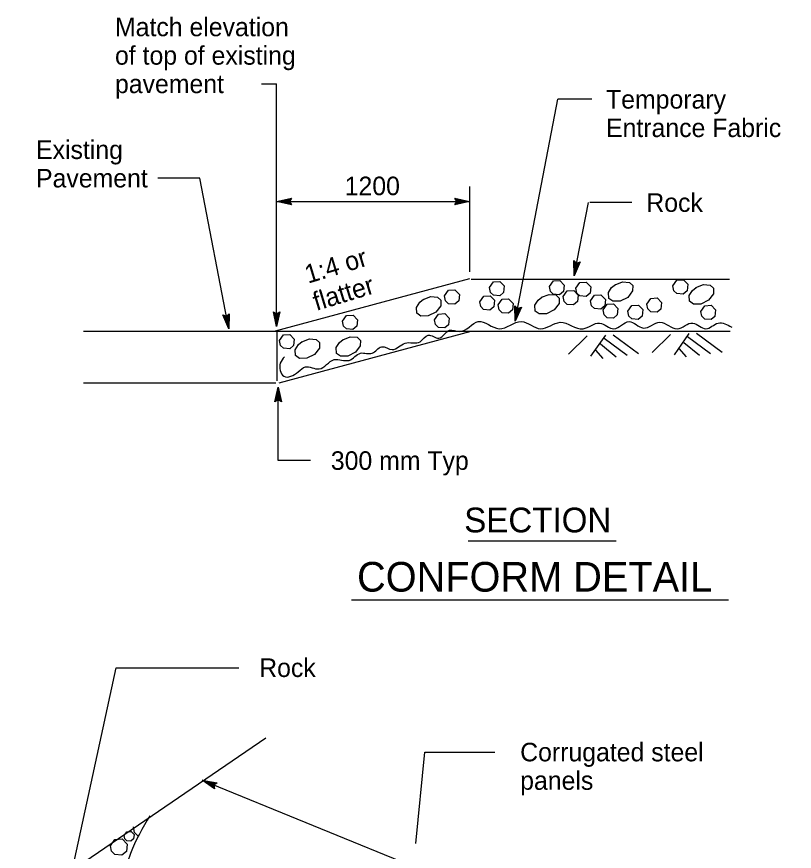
# Model space of a CAD drawing. Extents: x 6707406 to 6714471, y 1868570 to 1872341.
# Drawn here: x 6709787.7 to 6710089.4, y 1870437 to 1870760.9 of the extents above; entities that cross this region are included whole.
import ezdxf

# ---------------------------------------------------------------- set-up
doc = ezdxf.new("R2010")
doc.units = 0
for name, color, linetype in [('56 Stg 3 Anno', 7, 'Continuous'), ('57 Undefined', 7, 'Continuous'), ('59 Soundwall Ann', 7, 'Continuous'), ('60 Nongeo Data', 7, 'Continuous')]:
    doc.layers.add(name, color=color, linetype=linetype)

msp = doc.modelspace()

# ---------------------------------------------------------------- linework, layer by layer
at = {"layer": '56 Stg 3 Anno'}
for p, q in [((6709882.69, 1870734.85), (6709888.58, 1870734.85)), ((6709888.58, 1870640.62), (6709888.58, 1870734.85)), ((6709981.16, 1870642.76), (6709997.7, 1870728.84)), ((6710010.8, 1870728.84), (6709997.7, 1870728.84)), ((6709858.77, 1870698.25), (6709842.43, 1870698.25)), ((6709870.01, 1870639.76), (6709858.77, 1870698.25)), ((6709963.41, 1870695.06), (6709963.41, 1870661.92)), ((6709888.58, 1870689.24), (6709894.34, 1870690.52)), ((6709894.34, 1870690.52), (6709893.58, 1870689.24)), ((6709894.34, 1870690.52), (6709894.34, 1870690.52)), ((6709958.42, 1870689.24), (6709957.65, 1870690.53)), ((6709957.65, 1870690.53), (6709957.65, 1870690.53)), ((6709957.65, 1870690.53), (6709963.41, 1870689.24)), ((6709888.58, 1870689.24), (6709963.41, 1870689.24)), ((6709894.34, 1870687.95), (6709888.58, 1870689.24)), ((6709888.58, 1870689.24), (6709888.58, 1870689.24)), ((6709894.14, 1870688.3), (6709889.91, 1870689.24)), ((6709889.92, 1870689.24), (6709894.12, 1870690.17)), ((6709891.24, 1870689.24), (6709893.95, 1870689.84)), ((6709893.91, 1870688.64), (6709891.24, 1870689.24)), ((6709892.56, 1870689.24), (6709893.72, 1870689.49)), ((6709893.74, 1870688.97), (6709892.56, 1870689.24)), ((6709893.58, 1870689.24), (6709894.34, 1870687.95)), ((6709894.34, 1870687.95), (6709894.34, 1870687.95)), ((6709963.41, 1870689.24), (6709957.65, 1870687.96)), ((6709957.65, 1870687.96), (6709958.42, 1870689.24)), ((6709957.65, 1870687.96), (6709957.65, 1870687.96)), ((6709957.86, 1870690.19), (6709962.09, 1870689.24)), ((6709962.08, 1870689.24), (6709957.88, 1870688.31)), ((6709960.76, 1870689.24), (6709958.05, 1870688.64)), ((6709958.09, 1870689.84), (6709960.76, 1870689.24)), ((6709958.26, 1870689.51), (6709959.44, 1870689.24)), ((6709959.44, 1870689.24), (6709958.27, 1870688.99)), ((6709963.41, 1870689.24), (6709963.41, 1870689.24)), ((6710004.04, 1870660.38), (6710009.5, 1870688.77)), ((6710026.4, 1870688.77), (6710010.05, 1870688.77)), ((6710004.04, 1870660.38), (6710003.87, 1870666.28)), ((6710003.87, 1870666.28), (6710003.87, 1870666.28)), ((6710003.87, 1870666.28), (6710004.98, 1870665.28)), ((6710006.39, 1870665.79), (6710004.04, 1870660.38)), ((6710004.29, 1870661.69), (6710004.17, 1870665.99)), ((6710006.02, 1870665.65), (6710004.29, 1870661.68)), ((6710004.54, 1870662.98), (6710004.46, 1870665.76)), ((6710005.63, 1870665.5), (6710004.54, 1870662.98)), ((6710004.79, 1870664.28), (6710004.76, 1870665.47)), ((6710005.28, 1870665.39), (6710004.79, 1870664.28)), ((6710004.98, 1870665.28), (6710006.39, 1870665.79)), ((6710006.39, 1870665.79), (6710006.39, 1870665.79)), ((6710004.04, 1870660.38), (6710004.04, 1870660.38)), ((6709981.16, 1870642.76), (6709981, 1870648.65)), ((6709981, 1870648.65), (6709981, 1870648.65)), ((6709981, 1870648.65), (6709982.1, 1870647.66)), ((6709981.41, 1870644.07), (6709981.29, 1870648.37)), ((6709870.01, 1870639.76), (6709867.67, 1870645.17)), ((6709867.67, 1870645.17), (6709867.67, 1870645.17)), ((6709867.67, 1870645.17), (6709869.07, 1870644.66)), ((6709869.07, 1870644.66), (6709870.19, 1870645.66)), ((6709869.59, 1870645.1), (6709869.51, 1870642.36)), ((6709869.89, 1870645.39), (6709869.76, 1870641.06)), ((6709870.19, 1870645.66), (6709870.01, 1870639.76)), ((6709870.19, 1870645.66), (6709870.19, 1870645.66)), ((6709888.58, 1870640.62), (6709887.31, 1870646.38)), ((6709887.31, 1870646.38), (6709887.31, 1870646.38)), ((6709887.31, 1870646.38), (6709888.58, 1870645.61)), ((6709888.58, 1870641.95), (6709887.65, 1870646.15)), ((6709888.59, 1870643.27), (6709887.98, 1870645.98)), ((6709888.59, 1870644.6), (6709888.33, 1870645.76)), ((6709888.58, 1870645.61), (6709889.87, 1870646.38)), ((6709889.87, 1870646.38), (6709888.58, 1870640.62)), ((6709889.53, 1870646.17), (6709888.58, 1870641.94)), ((6709889.18, 1870645.94), (6709888.59, 1870643.27)), ((6709888.85, 1870645.78), (6709888.59, 1870644.6)), ((6709889.87, 1870646.38), (6709889.87, 1870646.38)), ((6709983.51, 1870648.17), (6709981.16, 1870642.76)), ((6709983.14, 1870648.03), (6709981.41, 1870644.06)), ((6709981.67, 1870645.36), (6709981.59, 1870648.14)), ((6709982.76, 1870647.88), (6709981.67, 1870645.36)), ((6709981.92, 1870646.66), (6709981.88, 1870647.85)), ((6709982.4, 1870647.77), (6709981.92, 1870646.66)), ((6709982.1, 1870647.66), (6709983.51, 1870648.17)), ((6709983.51, 1870648.17), (6709983.51, 1870648.17)), ((6709869.76, 1870641.07), (6709868.05, 1870645.02)), ((6709869.51, 1870642.36), (6709868.41, 1870644.91)), ((6709869.26, 1870643.67), (6709868.79, 1870644.76)), ((6709869.3, 1870644.88), (6709869.26, 1870643.67)), ((6709981.16, 1870642.76), (6709981.16, 1870642.76)), ((6709870.01, 1870639.76), (6709870.01, 1870639.76)), ((6709888.58, 1870640.62), (6709888.58, 1870640.62)), ((6709887.85, 1870611.42), (6709889.14, 1870617.18)), ((6709889.14, 1870588.65), (6709889.14, 1870617.18)), ((6709889.14, 1870617.18), (6709889.14, 1870617.18)), ((6709889.14, 1870617.18), (6709890.42, 1870611.42)), ((6709888.2, 1870611.63), (6709889.14, 1870615.86)), ((6709888.54, 1870611.86), (6709889.14, 1870614.53)), ((6709888.87, 1870612.03), (6709889.14, 1870613.21)), ((6709889.14, 1870615.85), (6709890.07, 1870611.65)), ((6709889.14, 1870614.53), (6709889.74, 1870611.82)), ((6709889.14, 1870613.21), (6709889.39, 1870612.05)), ((6709889.14, 1870612.19), (6709887.85, 1870611.42)), ((6709887.85, 1870611.42), (6709887.85, 1870611.42)), ((6709890.42, 1870611.42), (6709889.14, 1870612.19)), ((6709890.42, 1870611.42), (6709890.42, 1870611.42)), ((6709901.67, 1870588.65), (6709889.14, 1870588.65)), ((6709803.25, 1870401.82), (6709826.34, 1870508.28)), ((6709826.34, 1870508.28), (6709873.95, 1870508.28)), ((6709942.55, 1870440.07), (6709946.04, 1870475.53)), ((6709946.04, 1870475.53), (6709973.16, 1870475.53)), ((6709859.63, 1870464.61), (6710181.3, 1870333.54)), ((6709864.48, 1870461.25), (6709859.63, 1870464.61)), ((6709859.63, 1870464.61), (6709859.63, 1870464.61)), ((6709859.63, 1870464.61), (6709865.45, 1870463.62)), ((6709864.42, 1870461.64), (6709860.86, 1870464.11)), ((6709860.87, 1870464.11), (6709865.11, 1870463.39)), ((6709864.34, 1870462.05), (6709862.09, 1870463.61)), ((6709862.09, 1870463.61), (6709864.83, 1870463.14)), ((6709864.31, 1870462.42), (6709863.32, 1870463.11)), ((6709863.32, 1870463.11), (6709864.49, 1870462.91)), ((6709865.45, 1870463.62), (6709864.26, 1870462.73)), ((6709864.26, 1870462.73), (6709864.48, 1870461.25)), ((6709864.48, 1870461.25), (6709864.48, 1870461.25)), ((6709865.45, 1870463.62), (6709865.45, 1870463.62))]:
    msp.add_line(p, q, dxfattribs=at)
at = {"layer": '57 Undefined'}
for p, q in [((6709962.83, 1870557.57), (6710020.27, 1870557.57)), ((6709917.65, 1870534.57), (6710063.89, 1870534.57))]:
    msp.add_line(p, q, dxfattribs=at)
at = {"layer": '59 Soundwall Ann'}
for p, q in [((6710009.02, 1870637.04), (6710001.85, 1870629.93)), ((6710016.17, 1870637.38), (6710010.38, 1870629.14)), ((6710015.62, 1870636.16), (6710024.52, 1870629.61)), ((6710019.07, 1870637.51), (6710029.02, 1870630.18)), ((6710041.37, 1870637.64), (6710034.2, 1870630.53)), ((6710048.52, 1870637.98), (6710042.74, 1870629.74)), ((6710047.97, 1870636.76), (6710056.87, 1870630.21)), ((6710051.42, 1870638.11), (6710061.38, 1870630.78)), ((6710014.18, 1870633.9), (6710020.29, 1870628.92)), ((6710046.53, 1870634.5), (6710052.64, 1870629.52)), ((6710012.24, 1870631.52), (6710015.15, 1870628.32)), ((6710044.59, 1870632.11), (6710047.5, 1870628.92))]:
    msp.add_line(p, q, dxfattribs=at)
at = {"layer": '60 Nongeo Data'}
for p, q in [((6709888.11, 1870638.95), (6709963.56, 1870659.27)), ((6709964.03, 1870658.99), (6710064.27, 1870658.99)), ((6709813.68, 1870638.93), (6709888.86, 1870638.93)), ((6709888.67, 1870638.97), (6709888.67, 1870619.57)), ((6709888.86, 1870638.93), (6709964.59, 1870638.93)), ((6709889.53, 1870618.87), (6709964.03, 1870638.93)), ((6709964.03, 1870638.93), (6710064.55, 1870638.93)), ((6709813.68, 1870618.87), (6709888.3, 1870618.87)), ((6709495.94, 1870216.26), (6709884.38, 1870481.01))]:
    msp.add_line(p, q, dxfattribs=at)
for points in [[(6709971.13, 1870655.85), (6709972.68, 1870658.05), (6709975.15, 1870658.19), (6709976.87, 1870656.41), (6709976.62, 1870653.91), (6709975.1, 1870652.64), (6709972.65, 1870652.82), (6709971.5, 1870653.93), (6709971.13, 1870655.85)], [(6709994.38, 1870656.22), (6709995.93, 1870658.43), (6709998.41, 1870658.57), (6710000.13, 1870656.78), (6709999.88, 1870654.28), (6709998.35, 1870653.01), (6709995.91, 1870653.19), (6709994.76, 1870654.3), (6709994.39, 1870656.22)], [(6710019.9, 1870656.91), (6710022.8, 1870658.05), (6710025.46, 1870657.82), (6710026.73, 1870656.62), (6710026.69, 1870654.46), (6710024.77, 1870652), (6710021.8, 1870650.52), (6710019, 1870650.47), (6710017.42, 1870651.59), (6710017.27, 1870653.82), (6710018.55, 1870655.81), (6710020.02, 1870656.98)], [(6710042.34, 1870656.49), (6710043.89, 1870658.7), (6710046.36, 1870658.84), (6710048.08, 1870657.06), (6710047.84, 1870654.55), (6710046.31, 1870653.28), (6710043.86, 1870653.46), (6710042.71, 1870654.58), (6710042.34, 1870656.49)], [(6709953.71, 1870652.52), (6709955.26, 1870654.73), (6709957.74, 1870654.87), (6709959.46, 1870653.09), (6709959.21, 1870650.59), (6709957.68, 1870649.31), (6709955.23, 1870649.49), (6709954.08, 1870650.61), (6709953.71, 1870652.52)], [(6710004.68, 1870655.56), (6710006.23, 1870657.76), (6710008.71, 1870657.9), (6710010.43, 1870656.12), (6710010.18, 1870653.62), (6710008.65, 1870652.35), (6710006.21, 1870652.52), (6710005.06, 1870653.64), (6710004.68, 1870655.55)], [(6710051.24, 1870655.8), (6710054.14, 1870656.95), (6710056.8, 1870656.72), (6710058.07, 1870655.51), (6710058.03, 1870653.35), (6710056.11, 1870650.9), (6710053.14, 1870649.41), (6710050.34, 1870649.36), (6710048.76, 1870650.48), (6710048.62, 1870652.71), (6710049.89, 1870654.7), (6710051.36, 1870655.87)], [(6709945.44, 1870651.18), (6709948.34, 1870652.33), (6709951, 1870652.09), (6709952.27, 1870650.89), (6709952.23, 1870648.73), (6709950.3, 1870646.27), (6709947.33, 1870644.79), (6709944.54, 1870644.74), (6709942.96, 1870645.86), (6709942.81, 1870648.09), (6709944.09, 1870650.08), (6709945.55, 1870651.25)], [(6709967.35, 1870650.29), (6709968.9, 1870652.5), (6709971.38, 1870652.64), (6709973.1, 1870650.86), (6709972.85, 1870648.36), (6709971.32, 1870647.08), (6709968.88, 1870647.26), (6709967.73, 1870648.38), (6709967.36, 1870650.29)], [(6709991.38, 1870652.01), (6709994.28, 1870653.16), (6709996.94, 1870652.93), (6709998.21, 1870651.73), (6709998.17, 1870649.57), (6709996.25, 1870647.11), (6709993.28, 1870645.62), (6709990.48, 1870645.58), (6709988.9, 1870646.69), (6709988.76, 1870648.92), (6709990.03, 1870650.92), (6709991.5, 1870652.09)], [(6709999.79, 1870652.29), (6710001.34, 1870654.5), (6710003.82, 1870654.64), (6710005.54, 1870652.86), (6710005.29, 1870650.36), (6710003.76, 1870649.08), (6710001.32, 1870649.26), (6710000.17, 1870650.38), (6709999.79, 1870652.29)], [(6710010.39, 1870650.66), (6710011.94, 1870652.87), (6710014.41, 1870653.01), (6710016.13, 1870651.22), (6710015.88, 1870648.72), (6710014.35, 1870647.45), (6710011.91, 1870647.63), (6710010.76, 1870648.75), (6710010.39, 1870650.66)], [(6710032.17, 1870649.41), (6710033.73, 1870651.61), (6710036.2, 1870651.75), (6710037.92, 1870649.97), (6710037.67, 1870647.47), (6710036.14, 1870646.2), (6710033.7, 1870646.37), (6710032.55, 1870647.49), (6710032.18, 1870649.4)], [(6709974.57, 1870649.07), (6709976.12, 1870651.28), (6709978.59, 1870651.42), (6709980.31, 1870649.64), (6709980.06, 1870647.13), (6709978.54, 1870645.86), (6709976.09, 1870646.04), (6709974.94, 1870647.16), (6709974.57, 1870649.07)], [(6710015.24, 1870647.1), (6710016.79, 1870649.31), (6710019.27, 1870649.45), (6710020.98, 1870647.66), (6710020.74, 1870645.16), (6710019.21, 1870643.89), (6710016.76, 1870644.07), (6710015.61, 1870645.18), (6710015.24, 1870647.1)], [(6710024.88, 1870646.67), (6710026.43, 1870648.87), (6710028.9, 1870649.02), (6710030.62, 1870647.23), (6710030.37, 1870644.73), (6710028.85, 1870643.46), (6710026.4, 1870643.64), (6710025.25, 1870644.75), (6710024.88, 1870646.67)], [(6710053.12, 1870646.55), (6710054.67, 1870648.75), (6710057.14, 1870648.9), (6710058.86, 1870647.11), (6710058.62, 1870644.61), (6710057.09, 1870643.34), (6710054.64, 1870643.52), (6710053.49, 1870644.63), (6710053.12, 1870646.55)], [(6709914.17, 1870642.77), (6709915.72, 1870644.98), (6709918.2, 1870645.12), (6709919.92, 1870643.33), (6709919.67, 1870640.83), (6709918.14, 1870639.56), (6709915.69, 1870639.74), (6709914.55, 1870640.85), (6709914.17, 1870642.77)], [(6709949.81, 1870643.33), (6709951.36, 1870645.53), (6709953.84, 1870645.67), (6709955.56, 1870643.89), (6709955.31, 1870641.39), (6709953.78, 1870640.12), (6709951.34, 1870640.3), (6709950.19, 1870641.41), (6709949.81, 1870643.33)], [(6709889.67, 1870635.25), (6709891.22, 1870637.45), (6709893.69, 1870637.59), (6709895.41, 1870635.81), (6709895.16, 1870633.31), (6709893.64, 1870632.04), (6709891.19, 1870632.22), (6709890.04, 1870633.33), (6709889.67, 1870635.25)], [(6709898.38, 1870634.74), (6709901.28, 1870635.89), (6709903.94, 1870635.66), (6709905.21, 1870634.45), (6709905.17, 1870632.29), (6709903.25, 1870629.83), (6709900.28, 1870628.35), (6709897.48, 1870628.3), (6709895.9, 1870629.42), (6709895.76, 1870631.65), (6709897.03, 1870633.64), (6709898.5, 1870634.81)], [(6709914.25, 1870635.57), (6709917.15, 1870636.72), (6709919.82, 1870636.49), (6709921.08, 1870635.29), (6709921.04, 1870633.13), (6709919.12, 1870630.67), (6709916.15, 1870629.19), (6709913.35, 1870629.14), (6709911.78, 1870630.26), (6709911.63, 1870632.48), (6709912.9, 1870634.48), (6709914.37, 1870635.65)], [(6709829.39, 1870443.15), (6709830.43, 1870444.64), (6709832.1, 1870444.73), (6709833.25, 1870443.53), (6709833.09, 1870441.85), (6709832.06, 1870440.99), (6709830.41, 1870441.11), (6709829.64, 1870441.86), (6709829.39, 1870443.15)], [(6709834.9, 1870443.07), (6709834.76, 1870443.08), (6709833.47, 1870444.33), (6709833.05, 1870446.48)], [(6709824.11, 1870439.17), (6709825.85, 1870441.64), (6709828.62, 1870441.8), (6709830.56, 1870439.8), (6709830.28, 1870437), (6709828.56, 1870435.57), (6709825.82, 1870435.77), (6709824.53, 1870437.02), (6709824.11, 1870439.17)]]:
    msp.add_lwpolyline(points, dxfattribs=at)
for points in [[(6709891.64, 1870628.94), (6709889.97, 1870626.43), (6709889.97, 1870623.64), (6709891.36, 1870621.42), (6709896.93, 1870623.09), (6709899.71, 1870625.04), (6709905.01, 1870624.2), (6709910.85, 1870627.82), (6709916.7, 1870627.55), (6709921.15, 1870630.33), (6709925.61, 1870630.33), (6709929.23, 1870632.84), (6709933.41, 1870631.72), (6709938.42, 1870634.23), (6709944.27, 1870634.79), (6709947.33, 1870637.3), (6709951.51, 1870636.18), (6709955.68, 1870639.25), (6709959.58, 1870638.69), (6709966.82, 1870642.59), (6709974.89, 1870639.81), (6709983.53, 1870642.59), (6709991.04, 1870639.81), (6709998.56, 1870642.31), (6710007.47, 1870639.81), (6710013.88, 1870642.03), (6710019.44, 1870639.81), (6710025.29, 1870642.59), (6710030.86, 1870640.08), (6710037.27, 1870642.31), (6710043.95, 1870639.81), (6710050.07, 1870642.03), (6710055.09, 1870639.81), (6710059.82, 1870642.03), (6710065.11, 1870640.36)], [(6709839.39, 1870450.83), (6709831.86, 1870436.12), (6709837.31, 1870381.57), (6709845.79, 1870371.27)]]:
    msp.add_spline(points, degree=3, dxfattribs=at)

# ---------------------------------------------------------------- texts
at = {"layer": '57 Undefined'}
for s, height, p in [('Match elevation', 7.2002, (6709825.86, 1870753.33)), ('of top of existing', 7.2002, (6709825.86, 1870742.29)), ('pavement', 7.2, (6709825.86, 1870731.25)), ('Temporary', 7.2, (6710016.37, 1870725.24)), ('Entrance Fabric', 7.2002, (6710016.37, 1870714.2)), ('Existing', 7.2, (6709795.23, 1870705.69)), ('Pavement', 7.2, (6709795.23, 1870694.65)), ('1200', 7.2, (6709914.98, 1870691.64)), ('Rock', 7.2, (6710032, 1870685.17)), ('300 mm Typ', 7.2, (6709909.6, 1870585.05)), ('SECTION', 9.6, (6709961.35, 1870560.79)), ('CONFORM DETAIL', 11.5203, (6709919.77, 1870537.79)), ('Rock', 7.2, (6709881.8, 1870504.67)), ('Corrugated steel', 7.2002, (6709983.06, 1870471.93)), ('panels', 7.2, (6709983.06, 1870460.89))]:
    msp.add_text(s, height=height, dxfattribs=at).set_placement(p)
for s, p in [('1:4 or', (6709900.77, 1870657.28)), ('flatter', (6709903.98, 1870646.71))]:
    msp.add_text(s, height=7.2, rotation=16.9097, dxfattribs=at).set_placement(p)

doc.saveas('drawing.dxf')
